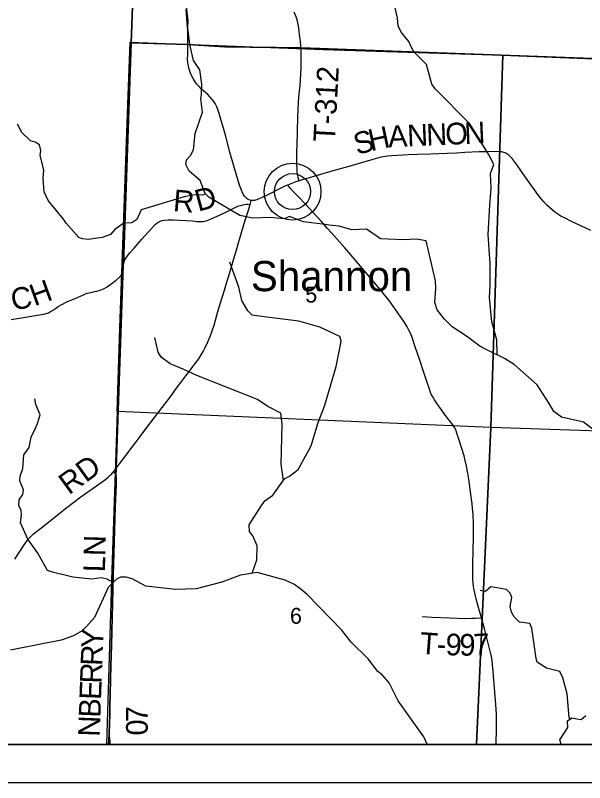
# Model space of a CAD drawing. Extents: x 0 to 34, y 0 to 22.
# Drawn here: x 5.757 to 7.248, y 14.3 to 16.31 of the extents above; entities that cross this region are included whole.
import ezdxf

# ---------------------------------------------------------------- set-up
doc = ezdxf.new("R2010")
doc.units = 0
for name, color, linetype in [('GM_X_County', 7, 'Continuous'), ('GM_X_County_Road', 7, 'Continuous'), ('GM_X_County_Road_Text', 7, 'Continuous'), ('GM_X_Minor_River', 7, 'Continuous'), ('GM_X_Section', 7, 'Continuous'), ('GM_X_Section_Text', 7, 'Continuous'), ('GM_X_Township', 7, 'Continuous'), ('GM_X_Township_Road', 7, 'Continuous'), ('GM_X_Township_Road_Text', 7, 'Continuous'), ('GM_X_Unincorporated', 7, 'Continuous'), ('GM_X_Unincorporated_Location', 7, 'Continuous'), ('GM_X_Unincorporated_Text', 7, 'Continuous'), ('SH_Data', 7, 'Continuous')]:
    doc.layers.add(name, color=color, linetype=linetype)

msp = doc.modelspace()

# ---------------------------------------------------------------- linework, layer by layer
at = {"layer": 'GM_X_County'}
msp.add_lwpolyline([(7.0736, 21.2003), (2.6013, 21.2003), (2.6013, 14.4003), (9.4013, 14.4003), (9.4013, 21.1598)], dxfattribs=at)
at = {"layer": 'GM_X_County_Road'}
for points in [[(6.2084, 16.2315), (6.2085, 16.2337), (6.2087, 16.254), (6.2083, 16.2701), (6.2068, 16.2889), (6.2038, 16.3254)], [(6.3743, 15.8247), (6.3713, 15.8256), (6.3686, 15.8267), (6.3662, 15.8278), (6.3636, 15.8296), (6.3612, 15.8317), (6.359, 15.8341), (6.3571, 15.8366), (6.3537, 15.8419), (6.3508, 15.8475), (6.3472, 15.8561), (6.344, 15.865), (6.3393, 15.8798), (6.3351, 15.8948), (6.3331, 15.9007), (6.3294, 15.9126), (6.3186, 15.9516), (6.3067, 15.9966), (6.3015, 16.0148), (6.2984, 16.0261), (6.2941, 16.0412), (6.2909, 16.053), (6.288, 16.0613), (6.2844, 16.0706), (6.2798, 16.0788), (6.2764, 16.0842), (6.2729, 16.0889), (6.2667, 16.0962), (6.2605, 16.1027), (6.2444, 16.1169), (6.2377, 16.1235), (6.2324, 16.1303), (6.228, 16.1362), (6.2227, 16.1445), (6.2181, 16.1529), (6.2156, 16.1589), (6.213, 16.1664), (6.2112, 16.1717), (6.2099, 16.1786), (6.2087, 16.1856), (6.2079, 16.1953), (6.2081, 16.2074), (6.2081, 16.2168), (6.2084, 16.2315)], [(7.2641, 15.7465), (7.2134, 15.7702), (7.1967, 15.7784), (7.1857, 15.7844), (7.1777, 15.7893), (7.17, 15.7946), (7.1625, 15.8003), (7.1554, 15.8064), (7.1487, 15.813), (7.1403, 15.8222), (7.1304, 15.8342), (7.121, 15.8467), (7.0905, 15.8898), (7.0707, 15.9178), (7.0578, 15.9351), (7.0538, 15.9397), (7.0493, 15.9438), (7.0469, 15.9457), (7.0443, 15.9473), (7.0417, 15.9487), (7.0389, 15.95), (7.036, 15.951), (7.0331, 15.9518), (7.0301, 15.9525), (7.0241, 15.953), (7.0148, 15.9532), (6.9931, 15.9528), (6.9714, 15.9522), (6.9342, 15.9506), (6.9125, 15.9495), (6.8876, 15.9485), (6.8442, 15.9466), (6.81, 15.9456), (6.7851, 15.9447), (6.7572, 15.9433), (6.7418, 15.9423), (6.7325, 15.9413), (6.7203, 15.9395), (6.7112, 15.9375), (6.6933, 15.9327), (6.6365, 15.9163), (6.5797, 15.9), (6.5319, 15.8863), (6.508, 15.8792), (6.4996, 15.8765)], [(6.4697, 15.8652), (6.4646, 15.8631), (6.4505, 15.8565), (6.4199, 15.8412), (6.4031, 15.833), (6.3945, 15.8291), (6.3887, 15.8268), (6.3857, 15.8259), (6.3826, 15.8251), (6.3806, 15.8249), (6.3775, 15.8247), (6.3743, 15.8247)], [(6.4996, 15.8765), (6.4909, 15.8736), (6.4783, 15.8689), (6.4697, 15.8652)], [(6.3713, 15.8148), (6.3743, 15.8247)], [(6.0132, 15.1134), (6.0186, 15.1206), (6.02, 15.1225), (6.0211, 15.1239), (6.0294, 15.1348), (6.0462, 15.1572), (6.0708, 15.1893), (6.0839, 15.2067), (6.0988, 15.2265), (6.1326, 15.2711), (6.1644, 15.3134), (6.1791, 15.3335), (6.1901, 15.3485), (6.2032, 15.3659), (6.2145, 15.3807), (6.2277, 15.398), (6.2369, 15.4105), (6.2437, 15.4209), (6.2484, 15.429), (6.2541, 15.4401), (6.2606, 15.4543), (6.2667, 15.4686), (6.2722, 15.4832), (6.2771, 15.498), (6.2874, 15.5338), (6.2934, 15.5547), (6.3043, 15.5904), (6.3099, 15.6081), (6.3144, 15.6222), (6.3161, 15.6279), (6.3265, 15.6634), (6.3362, 15.6962), (6.3492, 15.741), (6.3589, 15.7739), (6.3661, 15.7975), (6.3687, 15.8062), (6.3713, 15.8148)], [(5.7551, 14.8851), (5.7795, 14.9228), (5.7859, 14.9319), (5.7909, 14.9386), (5.7977, 14.9454), (5.8042, 14.9516), (5.8223, 14.9657), (5.8916, 15.021), (5.9283, 15.0483), (5.9837, 15.0876), (5.9937, 15.095), (6.0007, 15.101), (6.0052, 15.1052), (6.0092, 15.1092), (6.0132, 15.1134)]]:
    msp.add_lwpolyline(points, dxfattribs=at)
at = {"layer": 'GM_X_Minor_River'}
for points in [[(7.0189, 15.4203), (7.0175, 15.4596), (7.0047, 15.5073), (6.9987, 15.571), (7.0005, 15.6018), (7.0002, 15.6594), (6.9953, 15.7364), (6.9995, 15.8127), (7.0031, 15.8575), (7.001, 15.8954), (7.0096, 15.9194), (6.9958, 15.9466), (6.9458, 16.0268), (6.8563, 16.1179), (6.8475, 16.1296), (6.8337, 16.1815), (6.8002, 16.2144), (6.7936, 16.228), (6.7875, 16.242), (6.7677, 16.265), (6.7597, 16.2817), (6.7573, 16.3041), (6.7379, 16.389)], [(6.8324, 15.7194), (6.8074, 15.7238), (6.7744, 15.7218), (6.713, 15.7242), (6.6765, 15.7498), (6.6378, 15.7478), (6.6048, 15.7582), (6.5786, 15.7608), (6.568, 15.7619), (6.5111, 15.7688), (6.4751, 15.7831), (6.4614, 15.7766), (6.4231, 15.7806), (6.3784, 15.7789), (6.3443, 15.7856), (6.2637, 15.8341), (6.2542, 15.8436), (6.2411, 15.8773), (6.2122, 15.9022), (6.203, 15.9192), (6.2049, 15.9318), (6.2158, 15.9432), (6.2233, 15.958), (6.2277, 16.0002), (6.2467, 16.0564), (6.2424, 16.0917), (6.2442, 16.103), (6.2449, 16.1296), (6.2398, 16.1675), (6.2234, 16.1917), (6.2133, 16.2342), (6.2086, 16.2774), (6.2092, 16.2956), (6.2013, 16.3646)], [(6.2551, 15.8426), (6.2466, 15.839), (6.2239, 15.8397), (6.1989, 15.835), (6.0865, 15.8007), (6.0748, 15.7757), (6.062, 15.7661), (6.0411, 15.7653), (6.0173, 15.7489), (6.006, 15.7359), (5.9841, 15.7278), (5.9477, 15.7231), (5.9322, 15.7242), (5.9227, 15.7283), (5.8895, 15.7654), (5.8827, 15.776), (5.843, 15.8251), (5.8319, 15.8478), (5.8295, 15.8827), (5.8313, 15.9051), (5.822, 15.943), (5.8234, 15.9563), (5.8196, 15.9707), (5.8086, 15.9782), (5.7964, 15.9812), (5.7736, 16.0031), (5.7621, 16.0255)], [(7.2851, 15.2138), (7.2451, 15.2443), (7.1871, 15.2573), (7.1673, 15.2724), (7.1551, 15.2929), (7.123, 15.3424), (7.0632, 15.3949), (7.0382, 15.4107), (6.9948, 15.4322), (6.9846, 15.4374), (6.9728, 15.4431), (6.9386, 15.4698), (6.9006, 15.4943), (6.8804, 15.514), (6.8617, 15.5389), (6.8555, 15.5579), (6.858, 15.5951), (6.8568, 15.6144), (6.8324, 15.7194)], [(6.3773, 14.8483), (6.3891, 14.8835), (6.3897, 14.9199), (6.379, 14.9461), (6.3702, 14.9574), (6.3693, 14.9749), (6.4013, 15.0262), (6.4104, 15.0377), (6.4307, 15.0529), (6.4616, 15.0955), (6.4749, 15.1024), (6.4971, 15.1204), (6.5313, 15.182), (6.5493, 15.2405), (6.5672, 15.2884), (6.5967, 15.3902), (6.607, 15.4426), (6.6096, 15.4574), (6.6062, 15.4684), (6.5541, 15.4932), (6.4987, 15.5089), (6.4084, 15.5206), (6.3773, 15.5243), (6.3655, 15.5356), (6.3502, 15.5629), (6.3421, 15.5977), (6.3187, 15.6633)], [(6.4588, 15.0916), (6.4531, 15.1346), (6.4553, 15.2389), (6.4517, 15.2674), (6.4183, 15.2854), (6.3913, 15.3032), (6.2318, 15.3662), (6.1983, 15.3824), (6.1619, 15.397), (6.1383, 15.4147), (6.131, 15.4276), (6.1221, 15.4659)], [(6.0129, 14.8244), (5.9974, 14.8332), (5.9826, 14.8366), (5.9565, 14.8331), (5.9068, 14.8385), (5.8537, 14.8512), (5.8412, 14.8553), (5.8152, 14.9007), (5.7896, 14.9378), (5.7704, 14.9802), (5.773, 15.0007), (5.7718, 15.0125), (5.766, 15.0261), (5.7667, 15.0409), (5.7761, 15.0546), (5.7784, 15.0668), (5.7688, 15.0903), (5.7695, 15.1028), (5.7762, 15.1229), (5.7787, 15.1586), (5.7926, 15.1776), (5.7985, 15.205), (5.8098, 15.2285), (5.8147, 15.2407), (5.8218, 15.2635), (5.8103, 15.2904), (5.8079, 15.3052)], [(6.8353, 14.4003), (6.8269, 14.4195), (6.7593, 14.5144), (6.736, 14.5614), (6.7173, 14.5825), (6.7059, 14.5908), (6.6807, 14.6241), (6.6365, 14.6675), (6.6117, 14.6989), (6.5211, 14.7923), (6.5013, 14.8092), (6.4861, 14.8198), (6.4637, 14.83), (6.39, 14.8505), (6.3461, 14.8431), (6.2977, 14.8251), (6.2299, 14.8077), (6.1761, 14.8056), (6.0983, 14.8147), (6.063, 14.8335), (6.0467, 14.8384), (6.0319, 14.8383), (6.0217, 14.833), (5.9994, 14.8112), (5.9642, 14.7325), (5.9431, 14.7085), (5.9318, 14.6975), (5.9087, 14.6841), (5.8769, 14.6726), (5.744, 14.647)], [(7.2101, 14.4665), (7.2072, 14.4708), (7.2023, 14.5323), (7.1904, 14.5744), (7.1827, 14.591), (7.1478, 14.5996), (7.1234, 14.615), (7.1211, 14.6253), (7.1094, 14.7045), (7.1044, 14.717), (7.0767, 14.7203), (7.0634, 14.7339), (7.0561, 14.7468), (7.053, 14.7616), (7.0571, 14.7851), (7.0525, 14.7961), (7.0429, 14.8056), (7.002, 14.8126), (6.9884, 14.8008), (6.9743, 14.803)], [(7.1859, 14.4003), (7.1824, 14.4115), (7.2039, 14.4443), (7.203, 14.4613), (7.214, 14.4694), (7.2273, 14.4668), (7.2383, 14.4653), (7.2507, 14.4752)]]:
    msp.add_lwpolyline(points, dxfattribs=at)
at = {"layer": 'GM_X_Section'}
for p, q in [((5.9953, 14.4003), (6.9645, 14.4003)), ((6.9645, 14.4003), (7.9727, 14.4003))]:
    msp.add_line(p, q, dxfattribs=at)
for points in [[(6.5627, 16.2211), (7.0338, 16.2061), (7.0022, 15.2299), (6.0233, 15.2725), (6.0304, 15.4915), (6.0406, 15.7805), (6.0513, 16.0777), (6.0576, 16.2396)], [(7.0538, 16.2053), (7.5347, 16.1861), (8.0188, 16.1667), (8.0374, 16.1659), (8.0145, 15.1965), (7.0022, 15.2299), (7.0338, 16.2061)]]:
    msp.add_lwpolyline(points, close=True, dxfattribs=at)
for points in [[(6.9645, 14.4003), (7.0022, 15.2299), (6.0233, 15.2725), (6.0194, 15.164), (6.0094, 14.8571), (5.9953, 14.4003)], [(7.9727, 14.4003), (8.0145, 15.1965), (7.0022, 15.2299), (6.9645, 14.4003)]]:
    msp.add_lwpolyline(points, dxfattribs=at)
at = {"layer": 'GM_X_Township'}
for points in [[(6.2234, 21.2003), (6.1733, 19.6859), (6.1731, 19.6818), (6.1731, 19.6616), (6.1717, 19.6397), (6.1473, 18.845), (6.11, 17.7459), (6.0911, 17.2548), (6.0778, 16.7443), (6.0664, 16.4042), (6.0598, 16.2379), (6.2085, 16.2337), (6.3056, 16.228), (6.5048, 16.2253), (7.5772, 16.1862), (7.7357, 16.1804), (8.4842, 16.1527), (8.5405, 16.1503), (9.1818, 16.131), (9.4013, 16.1226)], [(2.6013, 16.5379), (2.6013, 14.4003), (6.0009, 14.4003)], [(6.0009, 14.4003), (6.0027, 14.4259), (6.0027, 14.4339), (6.003, 14.4487), (6.0041, 14.4859), (6.0043, 14.4952), (6.0044, 14.5045), (6.0046, 14.5294), (6.0056, 14.5728), (6.0066, 14.6039), (6.0081, 14.6598), (6.0109, 14.7685), (6.0128, 14.8431), (6.0155, 14.9301), (6.0173, 14.9922), (6.0182, 15.0233), (6.0204, 15.0791), (6.0208, 15.0946), (6.0206, 15.1008), (6.0201, 15.1039), (6.0211, 15.1239), (6.0394, 15.6545), (6.0396, 15.6603), (6.0598, 16.2379), (6.0664, 16.4042)], [(7.5772, 16.1862), (6.5048, 16.2253), (6.3056, 16.228), (6.2085, 16.2337), (6.0598, 16.2379), (6.0396, 15.6603), (6.0394, 15.6545), (6.0211, 15.1239), (6.0201, 15.1039), (6.0206, 15.1008), (6.0208, 15.0946), (6.0204, 15.0791), (6.0182, 15.0233), (6.0173, 14.9922), (6.0155, 14.9301), (6.0128, 14.8431), (6.0109, 14.7685), (6.0081, 14.6598), (6.0066, 14.6039), (6.0056, 14.5728), (6.0046, 14.5294), (6.0044, 14.5045), (6.0043, 14.4952), (6.0041, 14.4859), (6.003, 14.4487), (6.0027, 14.4339), (6.0027, 14.4259), (6.0009, 14.4003)], [(6.0009, 14.4003), (9.4013, 14.4003), (9.4013, 16.1226)]]:
    msp.add_lwpolyline(points, dxfattribs=at)
at = {"layer": 'GM_X_Township_Road'}
for points in [[(6.5048, 16.2251), (6.5048, 16.2253), (6.5046, 16.2284), (6.5031, 16.243), (6.5013, 16.2599), (6.4987, 16.2777), (6.4964, 16.2903), (6.4946, 16.2982), (6.4921, 16.3063), (6.4869, 16.3184)], [(6.4996, 15.8765), (6.499, 15.8795), (6.4977, 15.8856), (6.4961, 15.892), (6.495, 15.8996), (6.4944, 15.9092), (6.4941, 15.9206), (6.4939, 15.9323), (6.4943, 15.9537), (6.495, 15.9703), (6.4969, 16.0429), (6.4984, 16.0826), (6.5001, 16.1045), (6.5022, 16.1261), (6.5054, 16.1726), (6.5055, 16.213), (6.5048, 16.2251)], [(6.9773, 14.7317), (6.9693, 14.7589), (6.9657, 14.774), (6.9621, 14.7892), (6.9584, 14.8043), (6.9562, 14.8146), (6.9553, 14.8224), (6.9549, 14.8326), (6.9547, 14.8492), (6.9549, 14.8748), (6.9558, 14.9066), (6.9567, 14.9437), (6.9566, 14.9623), (6.9564, 14.9778), (6.9553, 15.0026), (6.9543, 15.0181), (6.9532, 15.0305), (6.9509, 15.049), (6.9445, 15.0951), (6.9421, 15.1104), (6.9385, 15.1287), (6.9351, 15.1438), (6.9319, 15.1558), (6.9188, 15.1973), (6.913, 15.215), (6.9099, 15.2238), (6.9073, 15.2294), (6.9058, 15.2321), (6.9023, 15.2371), (6.8928, 15.2494), (6.8834, 15.2618), (6.8725, 15.2769), (6.8616, 15.2921), (6.8547, 15.3024), (6.8499, 15.3104), (6.8469, 15.3159), (6.8443, 15.3216), (6.841, 15.3303), (6.8353, 15.348), (6.8268, 15.3747), (6.815, 15.4097), (6.805, 15.4391), (6.7949, 15.4685), (6.7915, 15.4772), (6.7876, 15.4856), (6.7832, 15.4938), (6.7766, 15.5043), (6.7644, 15.5223), (6.7465, 15.5478), (6.7353, 15.5627), (6.7119, 15.5917), (6.6801, 15.63), (6.6459, 15.6704), (6.6196, 15.701), (6.5928, 15.7313), (6.5741, 15.7521), (6.5575, 15.7706), (6.5366, 15.7936), (6.5154, 15.8164), (6.4983, 15.8344), (6.4855, 15.8479), (6.477, 15.8569), (6.473, 15.8615), (6.4697, 15.8652)], [(6.0393, 15.6535), (6.0394, 15.6545), (6.0404, 15.6606), (6.0412, 15.6636), (6.0422, 15.6665), (6.0434, 15.6694), (6.0449, 15.6721), (6.0466, 15.6747), (6.0501, 15.6797), (6.0577, 15.6889), (6.0676, 15.7002), (6.0877, 15.7237), (6.0964, 15.7331), (6.1232, 15.7618), (6.127, 15.7654), (6.13, 15.7678), (6.1328, 15.7695), (6.1357, 15.7708), (6.1386, 15.7718), (6.1416, 15.7726), (6.1477, 15.7737), (6.1573, 15.7747), (6.1701, 15.7747), (6.2206, 15.7718), (6.2324, 15.7702), (6.2403, 15.7696), (6.2452, 15.7699), (6.2486, 15.7702), (6.2527, 15.7711), (6.2587, 15.7727), (6.2674, 15.7761), (6.2928, 15.7876), (6.3096, 15.7957), (6.3291, 15.8053), (6.3377, 15.809), (6.3423, 15.8108), (6.3464, 15.8122), (6.3494, 15.8131), (6.3523, 15.8139), (6.3572, 15.8148), (6.3615, 15.8152), (6.3646, 15.8153), (6.3713, 15.8148)], [(5.7456, 15.513), (5.7676, 15.5171), (5.8196, 15.5257), (5.8347, 15.5285), (5.8377, 15.5292), (5.8407, 15.5301), (5.8435, 15.5311), (5.8464, 15.5324), (5.8491, 15.5338), (5.8542, 15.5371), (5.8618, 15.5425), (5.8691, 15.5475), (5.8747, 15.5509), (5.8801, 15.5537), (5.8882, 15.5578), (5.8933, 15.5602), (5.9001, 15.5632), (5.9104, 15.5671), (5.9175, 15.57), (5.923, 15.5727), (5.9274, 15.5748), (5.9347, 15.5781), (5.9405, 15.5809), (5.9447, 15.5823), (5.9487, 15.5834), (5.9579, 15.5852), (5.964, 15.5863), (5.9697, 15.5876), (5.9759, 15.5892), (5.9804, 15.5907), (5.9856, 15.5926), (5.9914, 15.5955), (5.9971, 15.599), (6.01, 15.6082), (6.0203, 15.6161), (6.0285, 15.6233), (6.0327, 15.628), (6.0344, 15.6305), (6.0358, 15.6332), (6.0367, 15.6355), (6.037, 15.6361), (6.0372, 15.6368), (6.0378, 15.6391), (6.0383, 15.6421), (6.0393, 15.6535)], [(6.0207, 15.0912), (6.0208, 15.0946), (6.0206, 15.1008), (6.0201, 15.1039), (6.0194, 15.1069), (6.0181, 15.1094), (6.0162, 15.1114), (6.0132, 15.1134)], [(6.0032, 14.4225), (6.0027, 14.4259), (6.0027, 14.4339), (6.003, 14.4487), (6.0041, 14.4859), (6.0043, 14.4952), (6.0044, 14.5045), (6.0046, 14.5294), (6.0056, 14.5728), (6.0066, 14.6039), (6.0081, 14.6598), (6.0109, 14.7685), (6.0128, 14.8431), (6.0155, 14.9301), (6.0173, 14.9922), (6.0182, 15.0233), (6.0204, 15.0791), (6.0207, 15.0912)], [(6.8222, 14.7346), (6.8481, 14.7336), (6.8946, 14.7313), (6.9337, 14.7298), (6.9522, 14.7303), (6.9615, 14.7308), (6.9773, 14.7317)], [(7.0157, 14.4003), (7.017, 14.442), (7.0172, 14.4638), (7.0168, 14.4793), (7.0152, 14.5041), (7.0084, 14.5908), (7.0065, 14.6093), (7.0045, 14.6247), (7.0027, 14.6338), (6.985, 14.7037), (6.9773, 14.7317)], [(6.0043, 14.4003), (6.0048, 14.4023), (6.0051, 14.4054), (6.0052, 14.4085), (6.0043, 14.4155), (6.0032, 14.4225)]]:
    msp.add_lwpolyline(points, dxfattribs=at)
at = {"layer": 'GM_X_Unincorporated'}
for radius in [0.0744, 0.0472]:
    msp.add_circle((6.4827, 15.8483), radius, dxfattribs=at)
at = {"layer": 'GM_X_Unincorporated_Location'}
msp.add_line((6.4827, 15.8483), (6.4827, 15.8483), dxfattribs=at)
at = {"layer": 'SH_Data'}
for p, q in [((2.6, 14.3997), (9.4, 14.3997)), ((2.5, 14.2997), (9.5, 14.2997))]:
    msp.add_line(p, q, dxfattribs=at)

# ---------------------------------------------------------------- texts
at = {"layer": 'GM_X_County_Road_Text'}
for s, height, rotation, p in [('N', 0.0568, 2.4304, (6.7839, 15.9667)), ('N', 0.0568, 2.4267, (6.8339, 15.9688)), ('O', 0.0568, 2.4267, (6.8838, 15.9709)), ('N', 0.0568, 2.4313, (6.9338, 15.973)), ('S', 0.0568, 15.6256, (6.6516, 15.944)), ('H', 0.0568, 12.0701, (6.6876, 15.9541)), ('A', 0.0568, 2.744, (6.7341, 15.9643)), ('RD', 0.05682, 35.99, (5.897, 15.0523))]:
    msp.add_text(s, height=height, rotation=rotation, dxfattribs=at).set_placement(p)
at = {"layer": 'GM_X_Section_Text'}
for s, p in [('5', (6.516, 15.5577)), ('6', (6.476, 14.7159))]:
    msp.add_text(s, height=0.0419, rotation=0, dxfattribs=at).set_placement(p)
at = {"layer": 'GM_X_Township_Road_Text'}
for s, height, rotation, p in [('T-312', 0.05682, 87.0077, (6.5937, 15.977)), ('R', 0.0568, 355.5501, (6.1685, 15.7973)), ('D', 0.0568, 14.9523, (6.2355, 15.7956)), ('H', 0.0568, 19.9271, (5.8067, 15.5474)), ('C', 0.0568, 9.6035, (5.7499, 15.5368)), ('LN', 0.05682, 88.4507, (5.9912, 14.8506)), ('Y', 0.0568, 87.9377, (5.9859, 14.6518)), ('T', 0.0568, 355.7962, (6.8146, 14.6377)), ('9', 0.0568, 358.2229, (6.8829, 14.6337)), ('9', 0.0568, 359.5897, (6.9194, 14.6326)), ('7', 0.0568, 3.0212, (6.9581, 14.6324)), ('-', 0.0568, 358.0406, (6.8594, 14.6345)), ('R', 0.0568, 87.94, (5.9842, 14.6051)), ('R', 0.0568, 87.9349, (5.9825, 14.5585)), ('E', 0.0568, 87.9373, (5.981, 14.516)), ('B', 0.0568, 87.9379, (5.9793, 14.4694)), ('7', 0.0568, 90.2991, (6.1033, 14.4584)), ('N', 0.0568, 87.9377, (5.9775, 14.4194)), ('0', 0.0568, 90.2568, (6.1035, 14.4233))]:
    msp.add_text(s, height=height, rotation=rotation, dxfattribs=at).set_placement(p)
at = {"layer": 'GM_X_Unincorporated_Text'}
msp.add_text('Shannon', height=0.07898, rotation=0, dxfattribs=at).set_placement((6.3735, 15.5875))

doc.saveas('drawing.dxf')
